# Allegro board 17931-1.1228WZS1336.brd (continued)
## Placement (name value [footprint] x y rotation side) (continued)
C5504  SC4D7U6D3V2MX-1-GP  [C402H22]  218.52 42.9 270 top
C5505  SC10U6D3V2MX-2-GP  [C402-TO0D2H28]  215.7 47.25 270 top
C5512  SCD1U25V2KX-GP  [C402H22]  216.91 37.89 0 top
C5513  SC1KP50V2KX-1DLGP  [C402H22]  216.15 37.87 0 top
C5514  SC10U25V5KX-DL-GP  [C805H58]  215.65 38.66 180 bottom
C5516  SCD1U25V2KX-GP  [C402H22]  160.76 108.03 180 bottom
C5517  SC10U6D3V2MX-2-GP  [C402-TO0D2H28]  159.16 108 180 bottom
C5520  SC4D7U6D3V2MX-1-GP  [C402H22]  154.42 106.76 90 bottom
C5521  SCD1U16V2KX-3GP  [C402H22]  215.19 55.05 270 bottom
C5522  SCD1U16V2KX-3GP  [C402H22]  215.19 52.69 270 bottom
C5523  SCD1U16V2KX-3GP  [C402H22]  215.19 51.92 270 bottom
C5524  SCD1U16V2KX-3GP  [C402H22]  215.19 54.26 270 bottom
C5525  SCD1U16V2KX-3GP  [C402H22]  215.19 53.5 270 bottom
C5526  SCD1U16V2KX-3GP  [C402H22]  215.19 55.81 270 bottom
C5528  SCD1U25V2KX-GP  [C402H22]  135.61 78.46 90 bottom
C5529  SCD1U16V2KX-3DLGP  [C402H22]  48.11 65.08 90 top
C5530  SCD1U16V2KX-3DLGP  [C402H22]  224.62 69.06 90 top
C5531  SC2200P50V2KX-2DLGP  [C402H22]  137.8 92.33 270 bottom
C5535  SC2200P50V2KX-2DLGP  [C402H22]  221.69 67.95 270 top
C5536  SC1U6D3V1MX-GP  [C0201H14]  217.66 40.67 180 top
C5538  SCD1U16V2KX-3DLGP  [C402H22]  218.29 40.67 180 top
C5539  SC470P50V2KX-3GP  [C402H22]  159.64 104.93 270 bottom
C5540  SC470P50V2KX-3GP  [C402H22]  159.64 105.69 270 bottom
C5541  SC1U6D3V1MX-GP  [C0201H14]  217.15 40.67 180 top
C5599  SC4D7U6D3V2MX-1-GP  [C402H22]  219.05 40.67 180 top
C5724  SCD01U50V2KX-1GP  [C402H22]  21.8 100.81 0 bottom
C5736  SCD1U16V2KX-3DLGP  [C402H22]  17.28 102.08 270 top
C5777  SCD1U16V2KX-3GP  [C402H22]  24.41 95.05 90 bottom
C5778  SCD1U16V2KX-3GP  [C402H22]  24.41 94.26 90 bottom
C5779  SCD1U16V2KX-3GP  [C402H22]  23.8 97.11 90 bottom
C5780  SCD1U16V2KX-3GP  [C402H22]  23.8 96.32 90 bottom
C5781  SCD1U16V2KX-3GP  [C402H22]  24.56 99.11 90 bottom
C5782  SCD1U16V2KX-3GP  [C402H22]  24.56 98.32 90 bottom
C5783  SCD1U16V2KX-3GP  [C402H22]  25.17 101.22 90 bottom
C5784  SCD1U16V2KX-3GP  [C402H22]  25.17 100.43 90 bottom
C5801  SCD1U16V2KX-3DLGP  [C402H22]  49.89 112.12 180 top
C5802  SCD1U16V2KX-3DLGP  [C402H22]  50.65 112.12 180 top
C5803  SCD1U16V2KX-3DLGP  [C402H22]  46.38 111.58 180 top
C5804  SCD1U16V2KX-3DLGP  [C402H22]  47.15 111.58 180 top
C5805  SCD1U16V2KX-3DLGP  [C402H22]  61.55 116.92 90 bottom
C5806  SCD1U16V2KX-3DLGP  [C402H22]  61.55 117.68 90 bottom
C5807  SCD1U16V2KX-3DLGP  [C402H22]  63.33 115.39 90 bottom
C5808  SCD1U16V2KX-3DLGP  [C402H22]  63.33 116.16 90 bottom
C5809  SCD1U25V2KX-GP  [C402H22]  52.61 117.98 180 bottom
C5810  SCD01U25V2KX-3DLGP  [C402H22]  45.37 119.99 0 top
C5811  SCD1U16V2KX-3DLGP  [C402H22]  43.82 115.44 270 top
C5812  SCD1U16V2KX-3DLGP  [C402H22]  56.34 115.27 90 top
C5813  SCD1U16V2KX-3DLGP  [C402H22]  55.32 119.48 45 bottom
C5854  SCD1U16V2KX-3DLGP  [C402H22]  57.43 116.79 270 top
C5862  SCD1U16V2KX-3DLGP  [C402H22]  57.43 116.03 270 top
C5863  SC2D2U10V2KX-GP  [C402H22]  52.99 113.89 90 bottom
C6007  SCD1U16V2KX-3DLGP  [C402H22]  156.59 39.04 270 top
C6008  SC10U10V2MX-DL-GP-U  [C402-TO0D2H28]  158.37 39.42 180 top
C6010  SCD01U25V2KX-3DLGP  [C402H22]  189.11 39.55 270 top
C6011  SCD01U25V2KX-3DLGP  [C402H22]  189.11 38.79 270 top
C6013  SCD01U25V2KX-3DLGP  [C402H22]  191.72 39.63 180 top
C6014  SCD01U25V2KX-3DLGP  [C402H22]  192.48 39.63 180 top
C6018  SC10U10V2MX-DL-GP-U  [C402-TO0D2H28]  187.12 33.9 0 top
C6019  SCD1U16V2KX-3DLGP  [C402H22]  186.28 33.85 0 top
C6028  SCD01U25V2KX-3DLGP  [C402H22]  165.36 38.79 180 top
C6029  SCD01U25V2KX-3DLGP  [C402H22]  164.6 38.79 180 top
C6030  SCD01U25V2KX-3DLGP  [C402H22]  163.71 38.79 180 top
C6031  SCD01U25V2KX-3DLGP  [C402H22]  162.94 38.79 180 top
C6102  SC4D7U6D3V3KX-L-GP  [C603H36]  47.76 102.29 270 top
C6104  SCD1U16V2KX-3DLGP  [C402H22]  31.42 105.23 180 top
C6105  SC10U6D3V3MX-DL-GP  [C603H36]  29.7 105.21 180 top
C6106  SCD1U25V2KX-1-DL-GP  [C402H22]  30.66 105.23 180 top
C6107  SCD1U16V2KX-3DLGP  [C402H22]  40.07 94.95 180 bottom
C6108  SCD1U16V2KX-3DLGP  [C402H22]  39.29 94.95 180 bottom
C6201  SCD1U16V2KX-3DLGP  [C402H22]  214.96 61.13 90 top
C6202  SCD1U16V2KX-3DLGP  [C402H22]  214.96 61.89 90 top
C6302  SCD22U10V2KX-2-GP  [C402H22]  24.31 35.08 0 bottom
C6303  SCD22U10V2KX-2-GP  [C402H22]  25.07 35.08 0 bottom
C6304  SC33P50V2JN-3DLGP  [C402H22]  20.4 21.59 90 top
C6305  SC33P50V2JN-3DLGP  [C402H22]  20.4 22.35 90 top
C6306  SCD047U25V2KX-4-GP  [C402H22]  39.65 30.43 0 bottom
C6307  SCD1U16V2KX-3DLGP  [C402H22]  38.87 30.43 0 bottom
C6308  SCD047U25V2KX-4-GP  [C402H22]  20.4 23.12 90 top
C6311  SCD22U10V2KX-2-GP  [C402H22]  27.31 35.41 0 bottom
C6312  SCD22U10V2KX-2-GP  [C402H22]  28.07 35.41 0 bottom
C6313  SCD22U10V2KX-2-GP  [C402H22]  30.31 35.6 0 bottom
C6314  SCD22U10V2KX-2-GP  [C402H22]  31.07 35.6 0 bottom
C6315  SCD22U10V2KX-2-GP  [C402H22]  33.33 35.08 0 bottom
C6316  SCD22U10V2KX-2-GP  [C402H22]  34.09 35.08 0 bottom
C6317  SC10U6D3V3MX-DL-GP  [C603H36]  40.21 28.49 180 bottom
C6318  SC10U6D3V3MX-DL-GP  [C603H36]  39.02 28.49 180 bottom
C6401  SCD1U16V2KX-3DLGP  [C402H22]  210.37 56.44 270 bottom
C6405  SC2D2U6D3V2MX-DL-GP  [C402H22]  50.98 68.2 180 top
C6501  SCD1U16V2KX-3GP  [C402H22]  85.39 37.69 90 top
C6502  SCD1U16V2KX-3DLGP  [C402H22]  93.25 32.21 180 bottom
C6505  SCD1U16V2KX-3GP  [C402H22]  102.49 29.16 180 top
C6506  SC10P50V2JN-4DLGP  [C402H22]  100.51 34.29 180 bottom
C6510  SC10P50V2JN-4DLGP  [C402H22]  88.45 37.72 90 top
C6511  SC10P50V2JN-4DLGP  [C402H22]  108.21 40.31 180 top
C7003  SCD1U16V2KX-3DLGP  [C402H22]  136.5 94.41 270 bottom
C7004  SC10U6D3V3MX-GP  [C603H38]  136.55 93.45 270 bottom
C7103  SCD1U16V2KX-3DLGP  [C402H22]  27.44 101.14 270 top
C7104  SCD1U16V2KX-3DLGP  [C402H22]  27.44 100.38 270 top
C7105  SCD1U16V2KX-3DLGP  [C402H22]  27.82 99.37 270 top
C7106  SCD1U16V2KX-3DLGP  [C402H22]  27.82 98.6 270 top
C7107  SCD1U16V2KX-3DLGP  [C402H22]  27.26 105.28 270 top
C7108  SCD1U16V2KX-3DLGP  [C402H22]  27.28 106.83 270 top
C7109  SCD1U16V2KX-3DLGP  [C402H22]  27.28 106.07 270 top
C7110  SCD1U16V2KX-3DLGP  [C402H22]  27.26 108.43 270 top
C7111  SCD1U16V2KX-3DLGP  [C402H22]  27.26 107.65 270 top
C7112  SCD1U16V2KX-3DLGP  [C402H22]  27.28 102.97 270 top
C7113  SCD1U16V2KX-3DLGP  [C402H22]  27.28 103.73 270 top
C7114  SCD1U16V2KX-3DLGP  [C402H22]  27.26 104.52 270 top
C7115  SCD1U16V2KX-3DLGP  [C402H22]  21.75 103.33 180 bottom
C7116  SCD1U16V2KX-3DLGP  [C402H22]  20.04 107.54 0 bottom
C7117  SCD1U16V2KX-3DLGP  [C402H22]  22.51 103.33 180 bottom
C7118  SCD1U16V2KX-3DLGP  [C402H22]  22.89 108.56 270 bottom
C7119  SC10U6D3V3MX-DL-GP  [C603H36]  21.09 107.82 180 bottom
C7120  SCD1U16V2KX-3DLGP  [C402H22]  33.94 121.46 180 top
C7161  SCD1U25V2KX-1-DL-GP  [C402H22]  17.58 104.09 90 top
C7162  SCD1U25V2KX-1-DL-GP  [C402H22]  17.58 104.85 90 top
C7163  SCD1U25V2KX-1-DL-GP  [C402H22]  17.58 105.72 90 top
C7164  SCD1U25V2KX-1-DL-GP  [C402H22]  17.58 106.5 90 top
C7165  SC2D2U6D3V2MX-DL-GP  [C402H22]  18.8 101.88 90 top
C7166  SCD1U25V2KX-1-DL-GP  [C402H22]  23.42 107.04 270 bottom
C7167  SCD33U6D3V1MX-GP  [C0201H13]  17.33 103.28 270 top
C7168  SCD33U6D3V1MX-GP  [C0201H13]  17.45 108.29 270 top
C7169  SCD33U6D3V1MX-GP  [C0201H13]  17.45 107.75 270 top
C7170  SCD33U6D3V1MX-GP  [C0201H13]  17.33 102.74 270 top
C7201  SCD1U25V2KX-1-DL-GP  [C402H22]  45.98 109.27 0 top
C7202  SC1U6D3V1MX-GP  [C0201H14]  41.79 107.19 0 top
C7203  SCD1U16V2KX-3DLGP  [C402H22]  38.49 106.03 270 top
C7204  SCD1U16V2KX-3DLGP  [C402H22]  38.49 107.63 270 top
C7205  SCD1U16V2KX-3DLGP  [C402H22]  43.96 125.45 180 top
C7206  SC10U6D3V2MX-2-GP  [C402-TO0D2H28]  44.87 125.54 180 top
C7207  SC1U10V2KX-1DLGP  [C402H22]  38.49 106.82 270 top
C7208  SC390P50V2KX-GP-U  [C402H24]  44.3 111.89 180 top
C7209  SC390P50V2KX-GP-U  [C402H24]  43.82 110.42 0 top
C7210  SCD1U16V2KX-3DLGP  [C402H22]  39.96 105.16 270 top
C7211  SCD1U16V2KX-3DLGP  [C402H22]  41.45 105.93 90 top
C7212  SC1U10V2KX-1DLGP  [C402H22]  41.45 105.14 90 top
C7213  SCD1U16V2KX-3DLGP  [C402H22]  43.69 113.06 90 top
C7214  SC1U50V3KX-GP  [C603H32]  49.75 127.04 90 top
C7215  SCD22U10V2KX-1GP  [C402H22]  59.21 135.21 270 top
C7216  SCD1U16V2KX-3DLGP  [C402H22]  52.16 129.01 180 top
C7217  SC2D2U6D3V2MX-DL-GP  [C402H22]  53.15 129.27 180 top
C7302  SCD1U25V2KX-1-DL-GP  [C402H22]  9.81 125.1 0 bottom
C7303  SCD1U25V2KX-1-DL-GP  [C402H22]  11.84 118.9 270 bottom
C7304  SCD1U25V2KX-1-DL-GP  [C402H22]  11.15 124.33 180 bottom
C7305  SC10U25V5KX-DL-GP  [C805H58]  12.35 113.54 270 bottom
C7306  SC1U50V3KX-1-GP  [C603H36]  12.02 120.35 90 top
C7307  SCD1U25V2KX-1-DL-GP  [C402H22]  11.84 118.11 270 bottom
C7401  SC1500P50V2KX-2-DL-GP  [C402H22]  33.57 124.27 0 top
C7403  SC22U6D3V3MX-1-DL-GP  [C603H40]  45.72 123.3 90 top
C7404  SC22U6D3V3MX-1-DL-GP  [C603H40]  44.99 122.1 90 top
C7405  SC1KP50V2KX-1GP  [C402H22]  39.18 120.6 0 top
C7601  SCD22U10V2KX-1GP  [C402H22]  122.24 139.61 225 bottom
C7602  SCD22U10V2KX-1GP  [C402H22]  121.68 139.05 225 bottom
C7603  SCD22U10V2KX-1GP  [C402H22]  122.81 140.17 225 bottom
C7604  SCD22U10V2KX-1GP  [C402H22]  123.36 140.73 225 bottom
C7605  SCD22U10V2KX-1GP  [C402H22]  123.94 141.3 225 bottom
C7606  SCD22U10V2KX-1GP  [C402H22]  124.48 141.85 225 bottom
C7607  SCD22U10V2KX-1GP  [C402H22]  125.04 142.41 225 bottom
C7608  SCD22U10V2KX-1GP  [C402H22]  125.61 142.98 225 bottom
C7610  SC4D7U6D3V2MX-1-GP  [C402H22]  132.44 151.11 45 bottom
C7611  SC4D7U6D3V3KX-GP  [C603H36]  121.02 142.13 180 bottom
C7612  SC1U6D3V1MX-GP  [C0201H14]  134.99 150.82 315 bottom
C7613  SC4D7U6D3V3KX-GP  [C603H36]  118.64 142.16 180 bottom
C7614  SC1U6D3V1MX-GP  [C0201H14]  127.43 147.75 270 top
C7615  SC4D7U6D3V3KX-DLGP  [C603H36]  124.15 131.22 315 top
C7616  SCD1U25V2KX-GP  [C402H22]  127.16 132.91 225 top
C7620  SC4D7U6D3V3KX-GP  [C603H36]  129.49 148.77 45 bottom
C7621  SC4D7U6D3V3KX-GP  [C603H36]  127.94 148.62 270 top
C7622  SC1U6D3V1MX-GP  [C0201H14]  129.72 150.32 315 bottom
C7623  SC10U6D3V3MX-GP  [C603H38]  122.24 144.17 0 bottom
C7624  SC4D7U6D3V3KX-DLGP  [C603H36]  123.32 132.05 315 top
C7625  SC10U6D3V3MX-GP  [C603H38]  131.45 150.72 45 bottom
C7626  SC22U6D3V3MX-1-GP  [C603H40]  119.83 142.13 180 bottom
C7627  SC10U6D3V3MX-GP  [C603H38]  130.2 150.39 180 top
C7628  SC22U6D3V3MX-1-GP  [C603H40]  129.04 150.39 180 top
C7629  SC10U6D3V3MX-GP  [C603H38]  130.12 135.75 135 top
C7630  SC1U6D3V1MX-GP  [C0201H14]  130.1 149.94 315 bottom
C7631  SC1U6D3V1MX-GP  [C0201H14]  130.48 149.56 315 bottom
C7632  SCD1U16V2KX-3GP  [C402H22]  129.14 137.45 315 top
C7633  SC1U6D3V1MX-GP  [C0201H14]  132.21 150.47 180 top
C7634  SC4D7U6D3V3KX-DLGP  [C603H36]  131.37 150.5 180 top
C7744  SC10U6D3V3MX-DL-GP  [C603H36]  143.71 102.88 270 top
C7745  SC10U6D3V3MX-DL-GP  [C603H36]  127.54 118.92 135 bottom
C7746  SC10U6D3V3MX-DL-GP  [C603H36]  126.7 119.76 135 bottom
C7801  SCD1U16V2KX-3GP  [C402H22]  136.99 128.28 225 top
C7802  SCD1U16V2KX-3GP  [C402H22]  138.71 130.02 225 top
C7805  SCD1U16V2KX-3GP  [C402H22]  136.42 132.14 315 top
C7807  SC1U6D3V1MX-GP  [C0201H14]  157.05 115.88 90 bottom
C7808  SCD1U16V2KX-3GP  [C402H22]  136.18 132.99 315 top
C7809  SCD1U16V2KX-3GP  [C402H22]  137.54 128.84 225 top
C7810  SC1U50V3KX-GP  [C603H32]  127.38 146.91 315 bottom
C7811  SC1U50V3KX-GP  [C603H32]  128.22 146.08 315 bottom
C7812  SC1U50V3KX-GP  [C603H32]  165.74 135.94 0 top
C7813  SC4D7U6D3V3KX-GP  [C603H36]  127.38 143.56 135 bottom
C7814  SC4D7U6D3V3KX-GP  [C603H36]  129.06 145.24 315 bottom
C7817  SC10U6D3V3MX-DL-GP  [C603H36]  126.55 144.4 135 bottom
C7818  SC22U6D3V3MX-1-GP  [C603H40]  134.03 133.15 315 top
C7819  SC10U6D3V3MX-GP  [C603H38]  152.4 149.15 0 top
C7820  SC22U6D3V3MX-1-GP  [C603H40]  155.4 151.74 180 top
C7821  SC22U6D3V3MX-1-GP  [C603H40]  156.72 151.74 180 top
C7822  SC22U6D3V3MX-1-GP  [C603H40]  161.04 151.69 180 top
C7823  SC10U6D3V3MX-GP  [C603H38]  163.2 115.11 0 top
C7824  SC10U6D3V3MX-GP  [C603H38]  154.08 151.74 180 top
C7825  SC1U50V3KX-GP  [C603H32]  164.47 115.11 0 top
C7826  SC1U50V3KX-GP  [C603H32]  164.47 135.94 0 top
C7827  SC1U50V3KX-GP  [C603H32]  154.05 115.11 0 top
C7828  SC1U50V3KX-GP  [C603H32]  156.85 115.11 0 top
C7829  SC10U6D3V3MX-GP  [C603H38]  165.74 130.1 180 top
C7902  SCD1U16V2KX-3GP  [C402H22]  129.64 126.72 315 top
C7905  SCD1U16V2KX-3GP  [C402H22]  132.96 123.97 45 top
C7906  SCD1U16V2KX-3GP  [C402H22]  133.51 124.51 45 top
C7907  SC18P50V2JN-1-GP  [C402H22]  154.34 111.34 180 bottom
C7908  SC18P50V2JN-1-GP  [C402H22]  155.28 108.9 0 bottom
C7934  SC4D7U6D3V3KX-GP  [C603H36]  132.06 127.05 135 top
C7935  SC22U6D3V3MX-1-GP  [C603H40]  131.22 127.89 135 top
C8001  SC4D7U6D3V3KX-GP  [C603H36]  152.79 103.16 90 top
C8002  SC4D7U6D3V3KX-GP  [C603H36]  132.34 131.47 135 top
C8003  SC4D7U6D3V3KX-GP  [C603H36]  164.7 111.71 270 bottom
C8004  SC4D7U6D3V3KX-GP  [C603H36]  150.26 118.15 180 bottom
C8008  SC4D7U6D3V3KX-GP  [C603H36]  127.63 129.62 315 top
C8009  SC4D7U6D3V3KX-GP  [C603H36]  134.7 131.14 315 top
C8010  SC22U6D3V3MX-1-GP  [C603H40]  149.36 111.61 90 top
C8011  SC1U6D3V1MX-GP  [C0201H14]  152.91 105.34 90 top
C8012  SC1U6D3V1MX-GP  [C0201H14]  129.16 133.27 315 top
C8013  SC1U6D3V1MX-GP  [C0201H14]  128.04 132.31 135 top
C8014  SC1U6D3V1MX-GP  [C0201H14]  130.22 134.33 135 top
C8015  SC4D7U6D3V3KX-GP  [C603H36]  132.9 129.57 135 top
C8016  SC4D7U6D3V3KX-GP  [C603H36]  131.02 132.99 315 top
C8017  SC22U6D3V3MX-1-GP  [C603H40]  136.95 130.53 135 top
C8018  SC1U6D3V1MX-GP  [C0201H14]  127.31 131.57 315 top
C8019  SC4D7U6D3V3KX-GP  [C603H36]  143.74 106.99 90 bottom
C8020  SC4D7U6D3V3KX-GP  [C603H36]  150.39 108.23 135 top
C8021  SC4D7U6D3V3KX-GP  [C603H36]  129.31 131.29 135 top
C8022  SC4D7U6D3V3KX-GP  [C603H36]  120.85 125.64 135 bottom
C8023  SC4D7U6D3V3KX-GP  [C603H36]  121.68 124.8 135 bottom
C8024  SC4D7U6D3V3KX-GP  [C603H36]  123.35 123.12 135 bottom
C8025  SC4D7U6D3V3KX-GP  [C603H36]  135.26 128.84 315 top
C8026  SC4D7U6D3V3KX-GP  [C603H36]  130.63 129.8 315 top
C8028  SC1U6D3V1MX-GP  [C0201H14]  135.56 124.28 45 top
C8029  SCD1U16V2KX-3GP  [C402H22]  134.14 123.55 315 top
C8030  SC4D7U6D3V3KX-GP  [C603H36]  122.53 123.98 135 bottom
C8031  SC4D7U6D3V3KX-GP  [C603H36]  152.8 104.35 90 top
C8032  SC4D7U6D3V3KX-GP  [C603H36]  143.71 105.42 270 top
C8034  SCD1U16V2KX-3GP  [C402H22]  162.36 111.94 0 bottom
C8035  SCD1U16V2KX-3GP  [C402H22]  148.88 117.13 270 bottom
C8036  SC1U6D3V1MX-GP  [C0201H14]  136.53 125.15 45 top
C8038  SC10U6D3V3MX-DL-GP  [C603H36]  125.02 121.44 135 bottom
C8039  SC10U6D3V3MX-DL-GP  [C603H36]  124.18 122.28 135 bottom
C8040  SC10U6D3V3MX-DL-GP  [C603H36]  143.71 104.15 270 top
C8041  SC10U6D3V3MX-DL-GP  [C603H36]  119.16 127.3 135 bottom
C8042  SC10U6D3V3MX-DL-GP  [C603H36]  125.86 120.6 135 bottom
C8043  SC10U6D3V3MX-DL-GP  [C603H36]  120.01 126.46 135 bottom
C8047  SC22U6D3V3MX-1-GP  [C603H40]  135.87 126.93 225 top
C8048  SC4D7U6D3V3KX-GP  [C603H36]  138.97 121.51 0 top
C8049  SCD1U16V2KX-3GP  [C402H22]  136.05 124.72 45 top
C8050  SC1U6D3V1MX-GP  [C0201H14]  134.95 125.1 315 top
C8051  SCD1U16V2KX-3GP  [C402H22]  136.88 127.31 225 top
C8101  SCD01U50V2KX-1GP  [C402H22]  152.28 119.69 90 top
C8103  SC820P50V2KX-1GP  [C402H22]  159.52 115.88 270 top
C8104  SC10U6D3V3MX-GP  [C603H38]  151.64 118.04 180 top
C8105  SC1U6D3V1MX-GP  [C0201H14]  155.4 115.88 90 bottom
C8106  SC1U6D3V1MX-GP  [C0201H14]  153.95 115.88 90 bottom
C8107  SC1U6D3V1MX-GP  [C0201H14]  154 129.34 90 bottom
C8108  SCD1U25V2KX-GP  [C402H22]  158.5 151.94 180 top
C8109  SC1U6D3V1MX-GP  [C0201H14]  155.65 151.56 90 bottom
C8110  SC1U6D3V1MX-GP  [C0201H14]  154.33 151.44 90 bottom
C8111  SC1U6D3V1MX-GP  [C0201H14]  163.3 115.88 270 bottom
C8112  SC1U6D3V1MX-GP  [C0201H14]  164.7 115.88 270 bottom
C8113  SC10U6D3V3MX-GP  [C603H38]  152.83 151.74 180 top
C8114  SC1U6D3V1MX-GP  [C0201H14]  159.08 113.89 0 top
C8115  SCD1U25V2KX-GP  [C402H22]  155.83 129.34 90 bottom
C8116  SCD1U25V2KX-GP  [C402H22]  162.06 151.18 180 top
C8117  SCD1U25V2KX-GP  [C402H22]  164.72 129.34 270 bottom
C8118  SCD1U25V2KX-GP  [C402H22]  157.61 151.56 90 bottom
C8119  SCD1U25V2KX-GP  [C402H22]  166.5 129.34 270 bottom
C8120  SCD1U25V2KX-GP  [C402H22]  163.2 136.58 270 bottom
C8121  SCD1U25V2KX-GP  [C402H22]  155.83 137.34 270 top
C8122  SCD1U25V2KX-GP  [C402H22]  166.63 136.58 270 bottom
C8123  SCD1U25V2KX-GP  [C402H22]  163.2 137.34 270 bottom
C8124  SCD1U25V2KX-GP  [C402H22]  164.85 137.34 270 bottom
C8125  SCD1U25V2KX-GP  [C402H22]  159.26 151.94 180 top
C8201  SCD01U50V2KX-1GP  [C402H22]  150.12 143.56 270 bottom
C8202  SC820P50V2KX-1GP  [C402H22]  161.19 151.59 270 bottom
C8204  SC1U6D3V1MX-GP  [C0201H14]  165.03 136.58 270 bottom
C8205  SC1U6D3V1MX-GP  [C0201H14]  166.68 137.47 270 bottom
C8206  SC1U6D3V1MX-GP  [C0201H14]  166.68 130.1 270 bottom
C8207  SC10U6D3V3MX-GP  [C603H38]  164.47 130.1 180 top
C8209  SCD1U25V2KX-GP  [C402H22]  164.72 130.1 270 bottom
C8210  SCD1U25V2KX-GP  [C402H22]  166.75 115.11 0 top
C8211  SCD1U25V2KX-GP  [C402H22]  154.31 150.8 90 bottom
C8212  SCD1U25V2KX-GP  [C402H22]  157.36 129.34 90 bottom
C8213  SCD1U25V2KX-GP  [C402H22]  165.1 150.8 270 bottom
C8214  SCD1U25V2KX-GP  [C402H22]  166.75 150.8 270 bottom
C8215  SC1U6D3V1MX-GP  [C0201H14]  163.3 129.21 270 bottom
C8216  SC1U6D3V1MX-GP  [C0201H14]  163.3 129.72 270 bottom
C8217  SC1U6D3V1MX-GP  [C0201H14]  166.55 115.88 270 bottom
C8218  SC10U6D3V3MX-GP  [C603H38]  165.74 115.11 0 top
C8219  SC1U6D3V1MX-GP  [C0201H14]  155.2 129.15 90 top
C8220  SCD1U25V2KX-GP  [C402H22]  165.99 150.8 270 top
C8221  SCD1U25V2KX-GP  [C402H22]  157.74 151.94 180 top
C8222  SCD1U25V2KX-GP  [C402H22]  155.07 115.24 0 top
C8223  SCD1U25V2KX-GP  [C402H22]  155.83 150.8 90 bottom
C8224  SC1U6D3V1MX-GP  [C0201H14]  154.31 137.43 270 top
C8225  SCD1U25V2KX-GP  [C402H22]  155.83 115.24 0 top
C8226  SCD1U25V2KX-GP  [C402H22]  163.07 137.47 90 top
C8501  SE33U25VM-11-GP  [CT7343H83]  136.15 84.38 180 bottom
C8502  ST22U25VBM-GP  [CT3528H79]  154.64 80.62 90 bottom
C8601  SC1U6D3V1MX-GP  [C0201H14]  167.21 111.46 0 bottom
C8603  SCD1U25V2KX-1-DL-GP  [C402H22]  163.12 111.94 0 bottom
C8605  SC470P50V2KX-3DLGP  [C402H22]  161.19 109.68 90 bottom
C8608  SC470P50V2KX-3DLGP  [C402H22]  161.19 110.49 90 bottom
C8625  SC10U6D3V3MX-GP  [C603H38]  162.92 107.44 180 bottom
C8626  SC10U6D3V3MX-GP  [C603H38]  161.72 107.01 180 bottom
C8627  SC1U6D3V1MX-GP  [C0201H14]  166.55 111.46 0 bottom
C8802  SCD1U16V2KX-L-GP  [C402H22]  97.49 149.86 180 top
C8803  SCD022U16V2KX-3GP  [C402H22]  109.58 150.8 0 top
C8804  SCD01U50V2KX-L-GP  [C402H22]  102.7 142.8 0 bottom
C8805  SCD1U16V2KX-L-GP  [C402H22]  94.03 145.29 270 top
C8806  SCD1U16V2KX-L-GP  [C402H22]  92.03 151.59 90 bottom
C8807  SCD1U16V2KX-L-GP  [C402H22]  101.55 142.01 0 top
C8808  SCD1U16V2KX-L-GP  [C402H22]  108.33 143.69 90 top
C8809  SCD1U16V2KX-L-GP  [C402H22]  100.89 147.06 90 top
C9104  SCD1U16V2KX-3DLGP  [C402H22]  159.54 81.87 0 top
C9106  SC10U6D3V3MX-DL-GP  [C603H36]  164.6 82.86 90 bottom
C9108  SCD1U16V2KX-3DLGP  [C402H22]  164.34 81.46 90 bottom
C9109  SC4D7U6D3V3KX-DLGP  [C603H36]  162.56 79.2 0 bottom
C9112  SCD1U16V2KX-3DLGP  [C402H22]  164.34 78.79 0 bottom
C9113  SCD1U16V2KX-3DLGP  [C402H22]  163.58 78.79 0 bottom
C9201  SC1U6D3V1MX-GP  [C0201H14]  222.56 65.58 180 top
C9202  SC1U6D3V1MX-GP  [C0201H14]  223.07 65.58 180 top
C9203  SCD1U16V2KX-3DLGP  [C402H22]  163.2 68.96 270 top
CPU1  WHISKEY-LAKE-GP  [BGA1528M2446-1H52]  91.24 95.17 270 bottom
D1701  RB520S30-GP  [SOD523AKH26]  146.06 67.37 180 top
D1702  BAW56-9-GP-U  [SOT23-2D4-312H44]  50.93 84.41 180 bottom
D2401  BAT54C-12-GP  [SOT-23-9H44]  21.69 41.23 180 bottom
D2402  L1SS355T1G-GP  [SOD323AKH44]  131.88 39.57 90 bottom
D2403  RB551V30-GP  [SOD323AKH38]  27.59 55.14 0 top
D2404  BAW56-9-GP-U  [SOT23-2D4-312H44]  50.93 81.48 180 bottom
D2501  BAT54C-12-GP  [SOT-23-9H44]  159.47 91.36 180 top
D2502  RB551V30-GP  [SOD323AKH38]  164.97 89.71 0 top
D2503  BAT54A-11-GP  [SOT-23-9H44]  157.94 92 180 bottom
D2601  RB551V30-GP  [SOD323AKH38]  162.87 85.7 90 top
D2703  BAT54C-12-GP  [SOT-23-9H44]  22.89 21.85 180 top
D2901  BAT54A-11-GP  [SOT-23-9H44]  24.77 6.66 0 top
D4001  L1SS355T1G-GP  [SOD323AKH44]  146.71 74.12 270 top
D4002  RB551V30-GP  [SOD323AKH38]  83.3 40.23 90 bottom
D4003  RB551V30-GP  [SOD323AKH38]  86.58 40.23 270 bottom
D4301  P6AF24A-R1-00001-GP  [D4724AKH44]  23.37 121.62 270 top
D4302  LBAV99LT1G-1-GP  [SOT23-2D4-312H44]  25.25 92.41 90 top
D4304  SMF18A-GP  [SOD123AK-2H43]  150.83 38.89 180 bottom
D4305  RB551V30-GP  [SOD323AKH38]  35.56 133.33 90 top
D5502  BAT54C-12-GP  [SOT-23-9H44]  157.23 79.43 0 top
D5503  BAT54C-12-GP  [SOT-23-9H44]  210.49 47.78 180 bottom
D5504  RB751S40T1G-GP  [D1608AK-UH28]  136.45 79.68 90 bottom
D5505  RB751S40T1G-GP  [D1608AK-UH28]  222.25 69.01 270 top
D5701  BAW56-9-GP-U  [SOT23-2D4-312H44]  18.7 90.96 0 top
D6401  BAT54A-11-GP  [SOT-23-9H44]  33.66 20.12 180 top
D6403  RB751VM-40TE-17-GP  [SOD323-2513AKH36]  50.8 64.9 0 top
D7201  SBA0520Q-R1-00001-GP-U  [D1006-0305AK-UH22]  53.32 127.76 0 top
D7202  SBA0520Q-R1-00001-GP-U  [D1006-0305AK-UH22]  54.68 127.2 270 top
D7401  SS3040HE-GP  [SOD123AK-3718-1H40]  41.13 125.83 270 top
D7902  L1SS355T1G-GP  [SOD323AKH44]  150.4 112.14 180 bottom
D8801  L1SS355T1G-GP  [SOD323AKH44]  99.34 143.21 270 bottom
D8803  L1SS355T1G-GP  [SOD323AKH44]  99.34 145.01 90 bottom
DBEC1  ACES-CON6-58-GP  [50696-00601-001]  46.54 74.58 90 top
DBG1  ACES-CON14-5-GP  [87212-1400N]  35.11 49.15 180 top
DCIN1  ACES-CON8-13-GP-U2  [50224-0080N-W02-U]  20.7 128.8 0 bottom
DM1  DDR4-260P-78-GP-U  [ADDR0206-P013A-1-U]  63.7 47 0 bottom
DM2  DDR4-260P-78-GP-U  [ADDR0206-P013A-1-U]  139.9 47 0 bottom
EC1202  SC2D2U6D3V2MX-DL-GP  [C402H22]  109.43 44.58 180 top
EC1203  SCD1U25V2KX-GP  [C402H22]  146.05 45.65 180 top
EC1303  SC2D2U6D3V2MX-DL-GP  [C402H22]  118.57 45.92 180 top
EC1707  SCD1U16V2KX-3DLGP  [C402H22]  157.13 74.56 180 top
EC1712  SCD1U16V2KX-3DLGP  [C402H22]  156.03 70.01 0 top
EC1801  SC10P50V2JN-4DLGP  [C402H22]  39.86 53.42 0 top
EC1803  SC4D7P50V2BN-2-GP  [C402H22]  102.62 76.56 90 top
EC1901  SC10P50V2JN-4DLGP  [C402H22]  26.19 21.02 90 top
EC1903  SC33P50V2JN-3DLGP  [C402H22]  27.87 20.73 90 top
EC2002  SC1KP50V2KX-1DLGP  [C402H22]  139.63 95.52 180 bottom
EC2201  SCD1U25V2KX-1-DL-GP  [C402H22]  100.69 98.07 270 top
EC2501  SC4D7P50V2BN-2-GP  [C402H22]  132.69 78.87 180 bottom
EC2502  SC4D7P50V2BN-2-GP  [C402H22]  129.31 89.84 90 bottom
EC2503  SC10P50V2JN-4DLGP  [C402H22]  131.93 78.87 180 bottom
EC2504  SC10P50V2JN-4DLGP  [C402H22]  135.64 89.71 90 top
EC2505  SC4D7P50V2BN-2-GP  [C402H22]  137.76 89.37 270 top
EC2506  SC4D7P50V2BN-2-GP  [C402H22]  134.85 80.11 90 top
EC2601  SC10P50V2JN-4DLGP  [C402H22]  30.15 56.97 270 top
EC2602  SC10P50V2JN-4DLGP  [C402H22]  27.44 52.76 0 top
EC2701  SC1KP16V2KX-DL-GP  [C402H22]  30.56 4.6 0 top
EC2702  SC1KP16V2KX-DL-GP  [C402H22]  22.94 4.22 0 top
EC2703  SC1KP16V2KX-DL-GP  [C402H22]  34.59 5.27 45 top
EC2704  SC1KP16V2KX-DL-GP  [C402H22]  20.78 20.35 180 top
EC2705  SC1KP16V2KX-DL-GP  [C402H22]  20.02 20.35 180 top
EC2706  SC22P50V2JN-4GP  [C402H22]  25.05 21.87 0 top
EC2707  SC22P50V2JN-4GP  [C402H22]  28.55 17.96 180 top
EC2708  SC22P50V2JN-4GP  [C402H22]  29.31 17.96 180 top
EC2901  SC1KP50V2KX-1DLGP  [C402H22]  19.51 2.82 0 top
EC2902  SC1KP50V2KX-1DLGP  [C402H22]  18.67 2.06 180 top
EC2903  SC1KP50V2KX-1DLGP  [C402H22]  18.34 5.08 0 top
EC2904  SC1KP50V2KX-1DLGP  [C402H22]  19.1 4.32 180 top
EC2905  SC1KP16V2KX-DL-GP  [C402H22]  17.38 11.81 90 top
EC2906  SC1KP16V2KX-DL-GP  [C402H22]  18.34 17.6 90 top
EC2907  SC680P50V2KX-2DLGP  [C402H22]  20.07 10.21 270 top
EC2908  SC680P50V2KX-2DLGP  [C402H22]  17.91 9.83 0 top
EC3513  SC1KP16V2KX-DL-GP  [C402H22]  18.11 56.87 180 bottom
EC4301  SC10U25V5KX-DL-GP  [C805H58]  17.06 126.64 270 top
EC4302  SC1KP50V2KX-1DLGP  [C402H22]  20.72 126.88 270 top
EC4306  SC10P50V2JN-4GP  [C402H22]  134.24 35.49 90 top
EC4307  SC1KP50V2KX-1DLGP  [C402H22]  144.58 40.87 270 bottom
EC4308  SC1KP50V2KX-1DLGP  [C402H22]  142.12 40.62 90 bottom
EC4309  SC10P50V2JN-4GP  [C402H22]  134.24 37.01 270 top
EC4310  SC10P50V2JN-4GP  [C402H22]  134.24 36.25 270 top
EC4311  SCD1U25V2KX-GP  [C402H22]  17.91 123.62 270 top
EC4312  SC1KP50V2KX-1DLGP  [C402H22]  20.7 128.48 270 top
EC4313  SC1KP50V2KX-1DLGP  [C402H22]  20.7 127.71 270 top
EC4534  SCD1U25V2KX-GP  [C402H22]  51.31 32.06 0 bottom
EC4701  SC1KP16V2KX-DL-GP  [C402H22]  71.38 102.41 180 top
EC5001  SC1KP16V2KX-DL-GP  [C402H22]  90.3 121.08 270 top
EC5503  SC33P50V2JN-3DLGP  [C402H22]  213.23 43.67 45 top
EC5504  SC33P50V2JN-3DLGP  [C402H22]  215.36 45.26 180 top
EC6401  SCD1U16V2KX-3GP  [C402H22]  211.71 55.55 270 top
EC6402  SCD1U25V2KX-1-DL-GP  [C402H22]  10.67 129.59 0 bottom
EC6403  SC1KP50V2KX-1DLGP  [C402H22]  210.19 55.55 90 top
EC6404  SCD1U25V2KX-1-DL-GP  [C402H22]  13.77 129.62 0 bottom
EC6405  SCD1U25V2KX-1-DL-GP  [C402H22]  201.67 56.09 180 bottom
EC6501  SC33P50V2JN-3GP  [C402H22]  108.97 37.14 270 top
EC6502  SC33P50V2JN-3GP  [C402H22]  103.48 31.01 270 top
EC6503  SC33P50V2JN-3GP  [C402H22]  110.49 37.14 90 top
EC6504  SC33P50V2JN-3GP  [C402H22]  106.18 35.82 90 top
EC6601  SC1KP16V2KX-DL-GP  [C402H22]  203.74 37.19 270 top
EC8901  SC1KP16V2KX-DL-GP  [C402H22]  55.32 46.69 180 top
EC8902  SC1KP16V2KX-DL-GP  [C402H22]  61.37 47.3 0 top
EC8903  SC1KP16V2KX-DL-GP  [C402H22]  110.19 44.58 180 top
EC8904  SC1KP16V2KX-DL-GP  [C402H22]  98.96 44.98 270 top
EC8905  SC1KP16V2KX-DL-GP  [C402H22]  68.81 76.68 0 top
EC8906  SC1KP16V2KX-DL-GP  [C402H22]  76.2 76.68 180 top
EC8907  SC1KP16V2KX-DL-GP  [C402H22]  84.61 76.51 180 top
EC8908  SC1KP16V2KX-DL-GP  [C402H22]  168.43 50.32 90 top
EC8909  SC1KP16V2KX-DL-GP  [C402H22]  92.15 75.67 180 top
EC8910  SC1KP16V2KX-DL-GP  [C402H22]  97.29 76.68 180 top
EC8911  SCD1U25V2KX-GP  [C402H22]  92.46 45.44 180 top
EC8912  SCD1U25V2KX-GP  [C402H22]  119.33 45.92 180 top
EC8913  SCD1U25V2KX-GP  [C402H22]  139.17 47.96 0 top
EC8914  SCD1U25V2KX-GP  [C402H22]  158.8 48.82 0 top
EC8915  SCD1U25V2KX-GP  [C402H22]  161.98 46.36 0 top
EC8923  SC1KP50V2KX-1GP  [C402H22]  110.82 123.95 180 top
EC8924  SC1KP50V2KX-1GP  [C402H22]  111.53 146.31 180 top
EC8925  SC1KP50V2KX-1GP  [C402H22]  105.51 139.52 270 top
EC8927  SCD1U25V2KX-GP  [C402H22]  94.36 141.02 270 top
EC8929  SC1KP50V2KX-1GP  [C402H22]  208.41 39.32 90 bottom
EC8930  SCD1U25V2KX-GP  [C402H22]  178.06 63.37 135 top
EC8932  SCD1U25V2KX-GP  [C402H22]  78.31 32.47 0 top
EC8933  SC1U10V2KX-1GP  [C402H22]  64.16 36.53 270 bottom
EC8934  SC1U10V2KX-1GP  [C402H22]  187.97 33.08 180 top
EC8935  SC1U10V2KX-1GP  [C402H22]  80.63 38.59 270 top
EC8936  SCD1U16V2KX-3GP  [C402H22]  204.8 59.73 270 top
EC8937  SC1U10V2KX-1GP  [C402H22]  156.21 36.5 180 top
EC8938  SC1U10V2KX-1GP  [C402H22]  155.45 36.5 180 top
EC8939  SC1U10V2KX-1GP  [C402H22]  64.16 37.29 270 bottom
EC8940  SCD1U16V2KX-3DLGP  [C402H22]  59.54 91.97 270 bottom
EC8941  SCD1U16V2KX-3DLGP  [C402H22]  41.66 68 0 top
EC8942  SCD1U16V2KX-3DLGP  [C402H22]  52.66 130.25 0 bottom
EC8943  SCD1U16V2KX-3DLGP  [C402H22]  47.88 101.32 270 top
EC8944  SCD1U16V2KX-3DLGP  [C402H22]  45.93 63.58 90 top
EC8945  SCD1U16V2KX-3DLGP  [C402H22]  177.04 58.47 90 top
EC8946  SCD1U16V2KX-3DLGP  [C402H22]  203 59.72 90 top
EC8947  SC1U10V2KX-1GP  [C402H22]  16.56 90.76 180 top
EC8948  SC1U10V2KX-1GP  [C402H22]  18.93 98.32 0 top
EC8949  SC1U10V2KX-1GP  [C402H22]  19.76 122.94 270 top
EC8950  SC1U6D3V1MX-GP  [C0201H14]  51.03 95.81 0 bottom
EC8951  SC1U6D3V1MX-GP  [C0201H14]  55.76 119.97 45 bottom
EC8952  SC1U6D3V1MX-GP  [C0201H14]  81.31 31.75 0 bottom
EC8953  SC1U6D3V1MX-GP  [C0201H14]  90.48 30.58 180 top
EC8955  SC1KP50V2KX-1GP  [C402H22]  176.36 65.05 135 top
EC8957  SCD1U25V2KX-GP  [C402H22]  80.57 32.97 270 bottom
EC8959  SC1U6D3V1MX-GP  [C0201H14]  45.72 101.7 0 top
EC8960  SC1U6D3V1MX-GP  [C0201H14]  197.11 34.34 0 top
EC8961  SC1KP16V2KX-DL-GP  [C402H22]  150.88 98.22 90 top
EC8962  SC1KP50V2KX-1GP  [C402H22]  140.74 38.33 270 top
EC8963  SCD1U25V2KX-GP  [C402H22]  196.83 40.9 270 top
EC8964  SCD1U25V2KX-GP  [C402H22]  178.62 62.84 315 top
EC8965  SC1KP16V2KX-DL-GP  [C402H22]  152.91 106.12 90 top
EC8966  SC1KP16V2KX-DL-GP  [C402H22]  138.28 97.95 0 top
EC8967  SC1KP16V2KX-DL-GP  [C402H22]  149.62 110.58 90 top
EC8968  SC1KP16V2KX-DL-GP  [C402H22]  130.05 113.38 315 top
EC8969  SC1KP50V2KX-1DLGP  [C402H22]  29.29 126.08 180 top
EC8971  SC1KP16V2KX-DL-GP  [C402H22]  200 54.43 180 top
EC8972  SC1KP16V2KX-DL-GP  [C402H22]  31.52 110.24 90 top
EC8973  SC1KP16V2KX-DL-GP  [C402H22]  204.47 54.54 90 top
EC8974  SCD1U25V2KX-GP  [C402H22]  199.24 54.43 180 top
EC8975  SC1U6D3V1MX-GP  [C0201H14]  171.99 43.54 90 top
EC8976  SCD1U25V2KX-GP  [C402H22]  204.49 53.72 90 top
EC8977  SC1U6D3V1MX-GP  [C0201H14]  51.54 95.81 0 bottom
EC8978  SC1U6D3V1MX-GP  [C0201H14]  56.14 120.35 45 bottom
EC8979  SC1U6D3V1MX-GP  [C0201H14]  80.8 31.75 0 bottom
EC8980  SC1U6D3V1MX-GP  [C0201H14]  89.97 30.58 180 top
EC8986  SC1U10V2KX-1GP  [C402H22]  194.06 34.34 0 top
EC8987  SC1U10V2KX-1GP  [C402H22]  175.8 37.34 0 top
EC8988  SC1U10V2KX-1GP  [C402H22]  110.37 30.38 180 top
EC8989  SC1U10V2KX-1GP  [C402H22]  96.8 34.06 90 top
EC8990  SC1U10V2KX-1GP  [C402H22]  21.29 24.33 0 top
EC8991  SC1U6D3V1MX-GP  [C0201H14]  147.65 33.38 270 top
EC8992  SC1U6D3V1MX-GP  [C0201H14]  131.6 32.56 45 top
EC8993  SC1U6D3V1MX-GP  [C0201H14]  109.53 29.64 180 top
EC8994  SC1U6D3V1MX-GP  [C0201H14]  54.08 31.12 180 top
EC8995  SC1U6D3V1MX-GP  [C0201H14]  76.36 41.28 180 top
EC8996  SC1U6D3V1MX-GP  [C0201H14]  168.46 40.29 270 top
EC8997  SC1U6D3V1MX-GP  [C0201H14]  132.39 103.3 270 top
EC8998  SC1U6D3V1MX-GP  [C0201H14]  172.47 47.96 90 top
EC8999  SC1U6D3V1MX-GP  [C0201H14]  42.14 30.44 90 bottom
EC9001  SC1U6D3V1MX-GP  [C0201H14]  57.51 37.11 90 top
ED301  AZ5125-02S-R7G-GP  [SOT23-2D4-312H46]  90.15 115.75 180 bottom
ED1217  PESD5V0U2BT-215-GP  [SOT23-2D4-312H44]  56.54 39.68 270 bottom
ED1302  PESD5V0U2BT-215-GP  [SOT23-2D4-312H44]  128.5 39.83 180 bottom
ED1701  PESD5V0S1BB-GP-U  [SOD-523-2H26]  159.49 79.3 180 bottom
ED1702  PESD5V0S1BB-GP-U  [SOD-523-2H26]  23.22 60.64 90 bottom
ED1703  PESD5V0S1BB-GP-U  [SOD-523-2H26]  61.45 137.82 270 bottom
ED1705  PESD5V0S1BB-GP-U  [SOD-523-2H26]  41.83 64.43 270 top
ED1706  PESD5V0S1BB-GP-U  [SOD-523-2H26]  31.55 56.03 180 top
ED1707  PESD5V0S1BB-GP-U  [SOD-523-2H26]  96.38 116.37 90 bottom
ED1801  PESD5V0S1BB-GP-U  [SOD-523-2H26]  166.93 65.18 90 top
ED1802  PESD5V0S1BB-GP-U  [SOD-523-2H26]  167.52 63.27 0 top
ED2403  AZ5125-02S-R7G-GP  [SOT23-2D4-312H46]  93.86 147.74 270 top
ED2910  AZ5125-02S-R7G-GP  [SOT23-2D4-312H46]  21.31 7.47 180 top
ED2911  AZ5125-02S-R7G-GP  [SOT23-2D4-312H46]  17.88 7.48 180 top
ED2912  AZ5125-02S-R7G-GP  [SOT23-2D4-312H46]  17.91 21.39 0 top
ED3201  AZ1043-04F-R7G-GP  [DFN10G2510H22]  40.65 84.41 90 bottom
ED3202  AZ1043-04F-R7G-GP  [DFN10G2510H22]  40.65 84.42 90 top
ED3501  AZ1043-04F-R7G-GP  [DFN10G2510H22]  17.07 53.29 270 bottom
ED3502  AZC099-04S-2-GP  [SOT-6H58]  17.91 47.04 270 bottom
ED3503  AZ1043-04F-R7G-GP  [DFN10G2510H22]  17.3 43.82 270 bottom
ED4303  AZ5725-01FDR7G-GP  [SOD882-10D6-1H20]  17.91 124.51 90 top
ED4304  LBAV99LT1G-1-GP  [SOT23-2D4-312H44]  124.97 37.3 180 bottom
ED4305  LBAV99LT1G-1-GP  [SOT23-2D4-312H44]  128.58 36.53 90 bottom
ED4306  LBAV99LT1G-1-GP  [SOT23-2D4-312H44]  124.97 39.82 180 bottom
ED5502  AZC099-04S-2-GP  [SOT-6H58]  214.18 48.16 270 bottom
ED5701  AZ1043-04F-R7G-GP  [DFN10G2510H22]  16.79 95.66 270 bottom
ED5702  AZ1043-04F-R7G-GP  [DFN10G2510H22]  16.87 98.71 90 bottom
ED5703  AZ1043-04F-R7G-GP  [DFN10G2510H22]  17.07 96.39 90 top
ED6001  AZ1043-04F-R7G-GP  [DFN10G2510H22]  164.21 36.12 0 top
ED6401  AZ5125-02S-R7G-GP  [SOT23-2D4-312H46]  211.48 54.48 0 bottom
ED6601  AZC099-04S-2-GP  [SOT-6H58]  202.5 41.16 90 bottom
ED7301  L05ESDL5V0NA-4-GP  [SLP2510P8-1H22]  11.69 116.18 270 bottom
ED7302  L05ESDL5V0NA-4-GP  [SLP2510P8-1H22]  11.31 127.31 270 bottom
ED7307  AZ5125-02S-R7G-GP  [SOT23-2D4-312H46]  18.09 121.51 270 top
ED7311  TVUFB0201AC0-GP  [SOD882-10D6-UH22]  11.61 122.51 90 bottom
ED7312  TVUFB0201AC0-GP  [SOD882-10D6-UH22]  10.09 122.51 270 bottom
ED7313  TVUFB0201AC0-GP  [SOD882-10D6-UH22]  13.62 121.31 180 bottom
ED7314  TVUFB0201AC0-GP  [SOD882-10D6-UH22]  13.62 119.79 0 bottom
ED7315  AZ5125-02S-R7G-GP  [SOT23-2D4-312H46]  11.94 118.16 180 top
ED9202  AZC099-04S-2-GP  [SOT-6H58]  207.78 55.45 270 bottom
EL3501  COIL-90OHM-100MHZ-5-GP  [L125100-4P-4H24]  18.95 49.79 270 bottom
EL3502  FILTER-4P-98-GP  [L125100-4P-5H24]  19.26 54.05 90 bottom
EL3503  FILTER-4P-98-GP  [L125100-4P-5H24]  19.28 52.5 90 bottom
EL3504  FILTER-4P-98-GP  [L125100-4P-5H24]  19.61 44.58 90 bottom
EL3505  FILTER-4P-98-GP  [L125100-4P-5H24]  19.59 42.98 90 bottom
EL3506  COIL-90OHM-100MHZ-5-GP  [L125100-4P-4H24]  21.82 46.33 180 bottom
EL4301  -  [0R0805-PAD]  24.08 127.46 90 top
EL4302  -  [0R0805-PAD]  24.08 129.26 90 top
EL4303  -  [0R0805-PAD]  17.53 128.96 180 top
EL4304  -  [0R0805-PAD]  17.48 122.56 180 bottom
EL5501  COIL-90OHM-100MHZ-5-GP  [L125100-4P-4H24]  213.16 49.79 180 top
EL5701  FILTER-4P-170-GP  [L125100-4P-3H24]  19.59 94.67 270 bottom
EL5702  FILTER-4P-170-GP  [L125100-4P-3H24]  19.61 96.22 270 bottom
EL5703  FILTER-4P-170-GP  [L125100-4P-3H24]  19.61 97.77 270 bottom
EL5704  FILTER-4P-170-GP  [L125100-4P-3H24]  19.61 99.34 270 bottom
EL6101  COIL-90OHM-100MHZ-5-GP  [L125100-4P-4H24]  31.78 97.64 0 top
EL6601  FILTER-4P-137-GP-U  [L125100-4P-4H28]  205.4 39.75 180 bottom
EL6602  FILTER-4P-137-GP-U  [L125100-4P-4H28]  205.41 41.31 180 bottom
EL7105  COIL-90OHM-100MHZ-5-GP  [L125100-4P-4H24]  28.58 117.81 180 top
EL7106  COIL-90OHM-100MHZ-5-GP  [L125100-4P-4H24]  36.22 116.89 270 top
ER2701  0R2J-2-GP  [R402H16]  26.85 19.25 0 top
ER5701  150R2F-1-GP  [R402H16]  15.05 94.72 0 bottom
ER5702  150R2F-1-GP  [R402H16]  15.05 96.42 0 bottom
ER5703  150R2F-1-GP  [R402H16]  15.05 98.12 0 bottom
ER5704  150R2F-1-GP  [R402H16]  15.05 99.82 0 bottom
F5503  POLYSW-1D1A24V-GP-U  [POLYSW-4633-UH43]  211.98 41.2 90 bottom
F5504  POLYSW-1D1A6V-9-GP-U  [POLYSW-2114H30]  157.36 99.24 180 bottom
F5505  POLYSW-1D1A6V-9-GP-U  [POLYSW-2114H30]  159.62 108.51 180 top
F5506  POLYSW-1D1A6V-9-GP-U  [POLYSW-2114H30]  224.39 40.87 270 top
F5701  POLYSW-1D1A6V-9-GP-U  [POLYSW-2114H30]  17.1 100.26 180 top
F6501  POLYSW-1D1A6V-9-GP-U  [POLYSW-2114H30]  80.83 36.6 180 bottom
FAN1  ACES-CON4-29-GP  [50224-0040N-001]  162.7 87.2 270 bottom
FC1102  SC2D2U6D3V2MX-DL-GP  [C402H22]  110.57 47.68 180 top
FC1103  SC2D2U6D3V2MX-DL-GP  [C402H22]  134.75 49.2 0 top
FC8901  SCD1U25V2KX-GP  [C402H22]  147.65 34.18 270 top
FC8902  SCD1U25V2KX-GP  [C402H22]  195.33 64.29 270 top
FC8903  SC1U10V2KX-1GP  [C402H22]  22.23 92.31 90 top
FC8904  SC1U6D3V1MX-GP  [C0201H14]  72.27 92.57 0 top
FC8905  SC1U6D3V1MX-GP  [C0201H14]  68.47 104.39 0 top
FC8906  SC1U6D3V1MX-GP  [C0201H14]  74.43 101.4 0 top
FC8907  SCD1U25V2KX-GP  [C402H22]  54.88 31.11 180 top
FC8908  SCD1U25V2KX-GP  [C402H22]  103 96.59 270 top
FC8909  SCD1U25V2KX-GP  [C402H22]  17.25 37.19 270 bottom
FC8910  SCD1U25V2KX-GP  [C402H22]  18.85 46.74 90 top
FC8911  SCD1U25V2KX-GP  [C402H22]  55.73 134.09 0 top
FC8912  SC68P50V2JN-1DLGP  [C402H22]  154.69 36.5 180 top
FC8913  SC68P50V2JN-1DLGP  [C402H22]  60.48 36.22 270 top
FC8914  SC68P50V2JN-1DLGP  [C402H22]  183.41 33.08 180 top
FC8915  SC68P50V2JN-1DLGP  [C402H22]  166.8 86.23 180 top
FC8916  SC68P50V2JN-1DLGP  [C402H22]  80.64 37.8 270 top
FC8917  SCD1U25V2KX-GP  [C402H22]  19.74 120.65 270 top
FC8918  SCD1U16V2KX-3GP  [C402H22]  160 108.03 180 bottom
FC8919  SCD1U16V2KX-3GP  [C402H22]  215.6 43.82 180 bottom
FC8921  SC68P50V2JN-1DLGP  [C402H22]  36.07 34.8 90 bottom
FC8922  SCD1U25V2KX-GP  [C402H22]  97.72 141.56 270 bottom
FC8923  SC68P50V2JN-1DLGP  [C402H22]  97.72 140.79 270 bottom
FC8924  SC68P50V2JN-1DLGP  [C402H22]  158.14 83.75 270 bottom
FC8929  SC68P50V2JN-1DLGP  [C402H22]  76.74 32.46 0 top
FC8930  SC68P50V2JN-1DLGP  [C402H22]  77.52 32.46 0 top
FC8931  SCD1U25V2KX-GP  [C402H22]  94.36 143.31 270 top
FC8932  SCD1U25V2KX-GP  [C402H22]  94.36 142.55 270 top
FC8933  SCD1U25V2KX-GP  [C402H22]  178.36 35.46 270 top
FC8934  SCD1U25V2KX-GP  [C402H22]  94.36 141.78 270 top
FC8935  SCD1U25V2KX-GP  [C402H22]  156.95 88.8 180 top
FC8936  SCD1U25V2KX-GP  [C402H22]  158.14 84.51 270 bottom
FC8937  SCD1U25V2KX-GP  [C402H22]  175.82 65.61 135 top
FC8938  SCD1U25V2KX-GP  [C402H22]  136.6 99.16 0 top
FC8939  SCD1U25V2KX-GP  [C402H22]  125.43 38.18 180 top
FC8940  SCD1U25V2KX-GP  [C402H22]  155.3 78.59 90 bottom
FC8941  SCD1U25V2KX-GP  [C402H22]  53.06 132.26 180 bottom
FC8942  SCD1U25V2KX-GP  [C402H22]  75.82 142.24 270 bottom
FC8944  SCD1U25V2KX-GP  [C402H22]  124.64 38.18 180 top
FC8945  SCD1U25V2KX-GP  [C402H22]  59.41 137.95 180 bottom
FC8946  SCD1U25V2KX-GP  [C402H22]  64.14 139.83 180 top
FC8947  SCD1U25V2KX-GP  [C402H22]  112.32 146.31 180 top
FC8948  SCD1U25V2KX-GP  [C402H22]  72.95 141.05 270 top
FC8951  SCD1U25V2KX-GP  [C402H22]  110.06 123.95 180 top
FC8952  SCD1U25V2KX-GP  [C402H22]  128.27 109.4 135 top
FC8953  SCD1U25V2KX-GP  [C402H22]  176.94 64.49 135 top
FC8954  SCD1U25V2KX-GP  [C402H22]  177.5 63.93 135 top
FC8955  SCD1U25V2KX-GP  [C402H22]  210.24 40.01 270 top
FC8956  SCD1U25V2KX-GP  [C402H22]  126.22 38.18 180 top
FC8957  SCD1U25V2KX-GP  [C402H22]  140.74 39.12 270 top
FC8958  SCD1U25V2KX-GP  [C402H22]  80.57 33.73 270 bottom
FC8959  SCD1U25V2KX-GP  [C402H22]  158.14 82.98 270 bottom
FC8960  SCD1U25V2KX-GP  [C402H22]  208.44 40.11 90 bottom
FC8961  SC1U10V2KX-1GP  [C402H22]  154.41 104.3 90 bottom
FC8962  SCD1U25V2KX-GP  [C402H22]  40.43 30.43 0 bottom
FC8963  SC1500P50V2KX-2-DL-GP  [C402H22]  215.38 37.87 0 top
FC8964  SC1500P50V2KX-2-DL-GP  [C402H22]  216.51 40.67 180 top
FC8965  SCD1U25V2KX-GP  [C402H22]  64.9 139.83 180 top
FC8966  SCD1U25V2KX-GP  [C402H22]  164.42 80.42 90 bottom
FC8967  SCD1U25V2KX-GP  [C402H22]  76.18 37.8 270 bottom
FC8970  SCD1U25V2KX-GP  [C402H22]  173.1 51.54 0 top
FC8981  SCD1U25V2KX-GP  [C402H22]  79.63 114.89 180 bottom
FC8983  SCD1U25V2KX-GP  [C402H22]  65.74 100.66 270 top
FC8984  SCD1U25V2KX-GP  [C402H22]  128.58 102.87 270 bottom
FC8985  SCD1U25V2KX-GP  [C402H22]  83.42 91.16 270 top
FC8986  SCD1U25V2KX-GP  [C402H22]  27.44 101.96 90 top
FC8987  SCD1U25V2KX-GP  [C402H22]  143.64 106.4 270 top
FC8988  SCD1U25V2KX-GP  [C402H22]  151.1 107.55 135 top
FC8990  SCD1U25V2KX-GP  [C402H22]  68.48 100.13 0 top
FC8991  SCD1U25V2KX-GP  [C402H22]  73.97 92.53 0 top
FC8992  SCD1U25V2KX-GP  [C402H22]  97.39 90.83 180 top
FC8993  SCD1U25V2KX-GP  [C402H22]  99.63 96.28 90 top
FC8994  SCD1U25V2KX-GP  [C402H22]  162.55 50.8 0 top
FC8995  SCD1U25V2KX-GP  [C402H22]  139.51 39.44 0 top
FC8996  SCD1U25V2KX-GP  [C402H22]  109.84 42.39 0 top
FC8997  SCD1U25V2KX-GP  [C402H22]  69.2 42.54 0 top
FC8998  SCD1U25V2KX-GP  [C402H22]  196.35 34.34 0 top
FC8999  SCD1U25V2KX-GP  [C402H22]  128.63 107.05 270 bottom
FC9001  SCD1U25V2KX-GP  [C402H22]  197.97 58.19 90 top
FC9002  SC1U10V2KX-1GP  [C402H22]  156.59 38.28 270 top
FC9003  SC1U10V2KX-1GP  [C402H22]  184.98 33.86 0 top
FC9004  SC1U10V2KX-1GP  [C402H22]  184.2 33.86 0 top
FC9005  SC1U6D3V1MX-GP  [C0201H14]  43.08 106.48 180 top
FC9006  SC1U6D3V1MX-GP  [C0201H14]  32.06 105.28 180 top
FP1  PTWO-CON8-11-GP  [FH52-8S-D5SH]  221.7 65.8 0 bottom
G1801  GAP-OPEN  [CON2O-U]  169.01 65.71 270 top
G6401  GAP-OPEN  [CON2O-U]  224.97 62.03 270 bottom
G6402  GAP-OPEN  [CON2O-U]  208.79 59.11 270 top
GPU1  N17S-G1-A1-GP  [BGA595M23H83]  133.57 131.98 45 bottom
H1  HOLE233R142-GP-U1  [HOLE233R142]  59.01 108.27 180 bottom
H2  HOLE233R142-GP-U1  [HOLE233R142]  59.01 83.97 180 bottom
H3  HOLE233R142-GP-U1  [HOLE233R142]  120.01 83.97 180 bottom
H4  HOLE233R142-GP-U1  [HOLE233R142]  120.01 108.27 180 bottom
H5  HOLE233R142-GP-U1  [HOLE233R142]  112.87 134.04 180 bottom
H6  HOLE233R142-GP-U1  [HOLE233R142]  145.65 148.93 180 bottom
H7  HOLE233R142-GP-U1  [HOLE233R142]  142.14 113.1 180 bottom
H9  HOLE335R178-GP  [HOLE335R178]  185.8 65.8 180 bottom
H10  HOLE335R178-GP  [HOLE335R178]  125.7 30.4 180 bottom
H11  HOLE256R115-GP  [HOLE256R115]  5.4 43.33 180 bottom
H12  HOLE335R229-GP  [HOLE335R229]  20.7 115.3 180 bottom
H13  HOLE256R115-GP  [HOLE256R115]  63.7 145.8 0 bottom
H14  HOLE256R115-GP  [HOLE256R115]  101.7 151.8 180 bottom
H16  HOLE335R178-GP  [HOLE335R178]  210.95 34.25 180 bottom
H17  HOLE256R115-GP  [HOLE256R115]  7.7 133.8 180 bottom
H18  HOLE256R115-GP  [HOLE256R115]  5.7 113.2 180 bottom
HDA27  ALC3204-CG-GP-U  [QFN40J5-G3D75H36]  26.93 13.77 0 top
HDD1  ACES-CON20-37-GP-U  [50406-02071-W01]  160.9 36.8 0 bottom
HDD2  STM-CON12-1-GP  [FFSKL05007N12C]  162.9 35.55 180 bottom
HDMI1  SKT-HDMI23-157-GP  [SKT-HDMI23-188139-2]  3.5 99.35 90 bottom
HPMIC1  AUDIO-JK677-GP  [14-00790-1A03-A]  3.41 15.2 90 bottom
HS3  STF237R113H86-GP  [STF237R113H86]  40.2 131.05 0 bottom
IOBD1  ACES-CON20-29-GP-U  [51530-02001-W01-U]  198.55 35.45 180 bottom
JUSB1  SKT-USB36-20-GP  [SKT-USB36-124102-1]  2.04 123.7 90 bottom
KB1  ACES-CON30-29-GP  [50699-03001-W01]  65.92 32.2 180 bottom
KBBL1  ACES-CON4-90-GP-U  [50698-00401-W01-U]  86.84 32.1 180 bottom
L7101  MCB1005H470FBP-GP  [L402H24]  17.88 108.36 180 bottom
L7602  MHC1608S121PBP-GP  [L603H38]  133.66 151.31 90 top
L7801  MHC1608S300QBP-GP  [L603H38]  131.8 134.83 225 top
L7901  MHC1608S300QBP-GP  [L603H38]  134.42 125.83 315 top
L7902  MCB1608S181FBP-GP  [L603H38]  132.56 125.8 315 top
LCD1  STAR-CON40-8-GP  [300E40-1010RA-G3]  221.7 47.3 270 bottom
LED1  LED-YW-5-GP  [LED3020-3P-19H44]  2.7 134.8 0 bottom
LED2  LED-Y-102-GP  [LED11516AKH28]  9.7 65.8 0 bottom
MESW1  SW-SLIDE3P-11-GP  [MSS3-Q-T-R]  13.15 43.33 270 bottom
NOREF  -  []  183.61 60.45 0 top
NOREF#2  -  []  6 85.85 0 top
NOREF#3  -  []  184.66 156.49 180 top
NOREF#4  -  []  157.49 38.65 0 top
NOREF#5  -  []  150.68 39.54 0 top
NOREF#6  -  []  138.38 109.76 90 top
NOREF#7  -  []  173.71 32.04 90 top
NOREF#8  *  [unnamed#2]  -1.74 4.41 0 top
NOREF#9  -  []  -0.25 67.47 90 top
NOREF#10  -  []  30.2 102.8 0 top
NOREF#11  -  []  160.9 36.8 90 top
NOREF#12  -  []  11.64 27 90 top
NOREF#13  -  []  13.14 27.5 90 top
NOREF#14  -  []  13.14 34.5 90 top
NOREF#15  -  []  51.4 96.63 90 top
NOREF#16  -  []  12.24 37.4 90 top
NOREF#17  *  [unnamed#2]  227.46 31.42 0 top
NOREF#18  -  []  85.51 18.05 180 top
NOREF#19  -  []  3.41 15.2 0 top
NOREF#20  -  []  153.75 37.13 0 top
NOREF#21  -  []  11.9 82.9 90 top
NOREF#22  -  []  148.34 28.49 90 top
NOREF#23  -  []  -11.3 15.8 0 top
NOREF#24  -  []  202.45 58.85 0 top
NOREF#25  -  []  192.55 60.8 0 top
NOREF#26  *  [unnamed#2]  40.64 4.41 0 top
NOREF#27  -  []  83.04 83.86 90 top
NOREF#28  -  []  147.77 36.81 0 top
NOREF#29  -  []  194.95 58.85 0 top
NOREF#30  -  []  21.33 46.51 90 top
NOREF#31  -  []  -11.3 15.8 0 top
NOREF#32  -  []  -1.48 39.31 0 top
NOREF#33  -  []  192.55 67.73 0 top
NOREF#34  -  []  53.29 105.98 0 top
NOREF#35  -  []  191.7 64.1 0 top
NOREF#36  -  []  199.7 60.8 90 top
NOREF#37  -  []  -2.69 56.78 0 top
NOREF#38  -  []  11.64 51.65 90 top
NOREF#39  -  []  -1.8 127.92 0 top
NOREF#40  -  []  51.4 96.63 90 top
NOREF#41  -  []  19.08 29.66 90 top
NOREF#42  -  []  51.4 104.88 0 top
NOREF#43  *  [unnamed#2]  89.59 150.7 0 top
NOREF#44  -  []  207.7 58.08 90 top
NOREF#45  -  []  5.44 47.8 90 top
NOREF#46  -  []  51.4 96.63 90 top
NOREF#47  -  []  164.8 34.85 90 top
NOREF#48  -  [unnamed#2]  -3.21 43.23 0 top
NOREF#49  -  []  152.9 27.48 90 top
NOREF#50  -  []  51.4 96.63 90 top
NOREF#51  -  []  30.2 102.8 0 top
NOREF#52  -  []  83.04 83.86 90 top
NOREF#53  -  []  192.55 60.8 90 top
NOREF#54  -  []  122.28 158.76 0 top
NOREF#55  -  []  177.8 41.37 0 top
NOREF#56  -  []  11.92 116.84 90 top
NOREF#57  -  []  152.9 27.48 90 top
NOREF#58  -  []  11.64 51.65 90 top
NOREF#59  -  []  4.01 10.35 0 top
NOREF#60  -  [unnamed#2]  228.54 147.42 0 top
NOREF#61  -  []  173.71 34.91 0 top
NOREF#62  -  []  3.41 15.2 0 top
NOREF#63  -  []  188 32.1 0 top
NOREF#64  -  []  183.39 50.73 0 top
NOREF#65  -  []  152.9 33.5 90 top
NOREF#66  -  []  82.3 64.31 0 top
NOREF#67  -  []  -0.25 67.47 90 top
NOREF#68  -  []  -1.8 127.92 0 top
NOREF#69  -  []  3.41 19.9 0 top
NOREF#70  -  []  195.8 62.75 0 top
NOREF#71  -  []  176.21 138.82 0 top
NOREF#72  -  []  51.4 96.63 90 top
NOREF#73  -  []  194.95 58.85 90 top
NOREF#74  -  []  19.08 54.31 90 top
NOREF#75  -  []  159.83 39.54 0 top
NOREF#76  -  []  116.29 159.31 0 top
NOREF#77  -  []  2.72 116.92 0 top
NOREF#78  -  []  -0.81 24.19 90 top
NOREF#79  -  []  189.17 33.8 90 top
NOREF#80  -  []  183.61 57.58 90 top
NOREF#81  -  []  4.01 10.35 90 top
NOREF#82  -  []  116.29 109.22 90 top
NOREF#83  -  []  11.92 116.84 90 top
NOREF#84  -  []  116.83 153.31 0 top
NOREF#85  -  [unnamed#2]  58.2 141.2 0 top
NOREF#86  -  []  5.28 22.36 0 top
NOREF#87  -  []  -1.48 63.96 0 top
NOREF#88  -  []  207.7 58.08 90 top
NOREF#89  -  []  168.31 28.49 90 top
NOREF#90  -  []  177.8 38.49 90 top
NOREF#91  -  []  5.57 11.29 90 top
NOREF#92  -  []  68.93 84.96 90 top
NOREF#93  -  []  3.41 15.2 0 top
NOREF#94  -  [unnamed#2]  3.7 7.3 0 top
NOREF#95  -  []  116.26 6.63 0 top
NOREF#96  -  []  4.01 10.35 90 top
NOREF#97  -  []  1.44 82.45 0 top
NOREF#98  -  []  13.14 30 90 top
NOREF#99  -  []  51.4 104.88 0 top
NOREF#100  -  []  12.24 24.6 90 top
NOREF#101  -  []  -0.25 67.47 90 top
NOREF#102  -  []  188 32.1 90 top
NOREF#103  -  []  3.41 15.2 90 top
NOREF#104  -  []  13.95 73.08 90 top
NOREF#105  -  []  12.85 80.22 0 top
NOREF#106  -  []  168.05 36.8 90 top
NOREF#107  -  []  176.15 39.28 90 top
NOREF#108  -  []  190.07 48.19 0 top
NOREF#109  -  []  2.75 68.25 90 top
NOREF#110  -  []  157.49 28.49 90 top
NOREF#111  -  []  21.33 21.86 90 top
NOREF#112  -  []  3.41 19.9 0 top
NOREF#113  -  []  51.4 96.63 90 top
NOREF#114  -  [unnamed#2]  81.3 4.87 0 top
NOREF#115  -  []  12.24 49.25 90 top
NOREF#116  -  []  178.25 67.73 0 top
NOREF#117  -  []  51.4 96.63 90 top
NOREF#118  -  []  2.72 116.92 0 top
NOREF#119  -  []  68.24 83.17 0 top
NOREF#120  -  []  68.93 84.96 90 top
NOREF#121  -  []  177.4 58.08 90 top
NOREF#122  -  []  138.38 110.26 90 top
NOREF#123  -  []  194.95 58.85 90 top
NOREF#124  -  []  5.28 47.01 0 top
NOREF#125  -  []  122.28 158.76 0 top
NOREF#126  -  []  148.34 38.65 0 top
NOREF#127  -  []  190.07 44.05 90 top
NOREF#128  -  []  51.4 96.63 90 top
NOREF#129  -  []  157 34.85 0 top
NOREF#130  -  []  -3.99 26.86 0 top
NOREF#131  -  []  182.43 38.28 0 top
NOREF#132  -  []  168.31 28.49 90 top
NOREF#133  -  []  186.83 41.3 0 top
NOREF#134  -  []  153.75 36.8 0 top
NOREF#135  -  []  157.65 38.75 0 top
NOREF#136  -  []  177.4 58.08 90 top
NOREF#137  -  []  13.14 54.65 90 top
NOREF#138  -  []  199.7 60.8 90 top
NOREF#139  -  []  138.38 109.76 90 top
NOREF#140  -  []  228.48 126.8 270 top
NOREF#141  -  []  -2.1 11.29 0 top
NOREF#142  -  []  5.44 23.15 90 top
NOREF#143  -  []  68.93 84.31 0 top
NOREF#144  -  []  116.29 159.31 0 top
NOREF#145  -  [unnamed#2]  196.4 71.76 0 top
NOREF#146  -  []  186.83 41.3 0 top
NOREF#147  -  [unnamed#2]  105.05 14.71 0 top
NOREF#148  -  []  51.4 96.63 90 top
NOREF#149  -  []  120.53 58.6 0 top
NOREF#150  -  []  177.4 64.1 0 top
NOREF#151  -  []  12.85 80.22 0 top
NOREF#152  -  []  172.06 32.82 90 top
NOREF#153  -  []  202.45 58.85 0 top
NOREF#154  -  []  184.52 39.93 90 top
NOREF#155  -  []  194.95 58.85 0 top
NOREF#156  -  []  148.34 28.49 90 top
NOREF#157  -  []  -0.14 18.9 0 top
NOREF#158  -  []  3.7 7.3 0 top
NOREF#159  -  []  12.24 62.05 90 top
NOREF#160  -  []  -0.25 67.47 90 top
NOREF#161  -  []  53.29 105.98 0 top
NOREF#162  -  []  -1.8 127.92 0 top
NOREF#163  -  []  72.19 82.17 0 top
NOREF#164  -  [unnamed#2]  -0.21 151.42 0 top
NOREF#165  -  []  184.39 59.23 0 top
NOREF#166  -  []  11.64 59.65 90 top
NOREF#167  *  [unnamed#2]  195.33 151.94 0 top
NOREF#168  -  []  5.44 47.8 90 top
NOREF#169  -  []  30.89 105.98 0 top
NOREF#170  -  []  13.14 52.15 90 top
NOREF#171  *  [unnamed#2]  5.57 150.03 0 top
NOREF#172  -  []  97.51 4.29 0 top
NOREF#173  -  []  -2.06 85.96 0 top
NOREF#174  -  []  4.85 86.35 90 top
NOREF#175  -  []  3.41 19.9 90 top
NOREF#176  -  []  -3.99 15.2 90 top
NOREF#177  *  [unnamed#2]  221.22 139.87 0 top
NOREF#178  -  []  5.44 23.15 90 top
NOREF#179  -  []  -7.69 18.9 0 top
NOREF#180  -  []  116.83 153.31 0 top
NOREF#181  -  []  159.16 28.49 90 top
NOREF#182  -  []  4.01 10.35 0 top
NOREF#183  -  []  192.55 60.8 90 top
NOREF#184  -  []  114.56 57.96 0 top
NOREF#185  -  []  116.83 115.21 90 top
NOREF#186  -  []  72.19 82.17 0 top
NOREF#187  -  []  13.14 59.15 90 top
NOREF#188  -  []  11.64 27 90 top
NOREF#189  -  []  -0.81 48.84 90 top
NOREF#190  -  []  -0.25 79.55 0 top
NOREF#191  -  []  156.92 36.81 0 top
NOREF#192  -  []  2.75 85.05 90 top
NOREF#193  -  []  -2.69 32.13 0 top
NOREF#194  -  []  68.24 83.17 0 top
NOREF#195  -  []  192.55 60.8 0 top
NOREF#196  -  []  -0.81 48.84 0 top
NOREF#197  -  []  68.93 84.31 0 top
NOREF#198  *  [unnamed#2]  8.51 2.41 0 top
NOREF#199  -  []  -11.91 21.69 90 top
NOREF#200  -  []  116.83 115.21 90 top
NOREF#201  -  []  3.41 19.9 0 top
NOREF#202  -  []  83.04 83.86 90 top
NOREF#203  -  []  199.7 60.8 90 top
NOREF#204  *  [unnamed#2]  157.05 111.08 0 top
NOREF#205  -  []  116.29 109.22 90 top
NOREF#206  -  []  -3.99 26.86 0 top
NOREF#207  -  []  2.75 85.05 0 top
NOREF#208  -  []  -0.81 24.19 0 top
NOREF#209  -  []  3.41 19.9 90 top
NOREF#210  -  []  152.9 33.5 0 top
NOREF#211  -  []  186.83 40.3 90 top
NOREF#212  -  []  11.92 116.84 90 top
NOREF#213  -  []  185.73 59.05 0 top
NOREF#214  -  []  186.83 41.3 0 top
NOREF#215  -  []  68.93 84.96 90 top
NOREF#216  -  []  232.5 140.6 0 top
NOREF#217  -  []  2.72 116.92 0 top
NOREF#218  -  []  29 104.88 0 top
NOREF#219  -  []  135.87 60.58 0 top
NOREF#220  -  []  156.15 38.75 0 top
NOREF#221  -  []  12.85 80.22 90 top
NOREF#222  -  []  184.52 42.8 0 top
NOREF#223  -  []  199.7 60.8 90 top
NOREF#224  -  []  138.38 110.26 90 top
NOREF#225  -  []  11.64 35 90 top
NOREF#226  -  []  30.2 102.8 0 top
